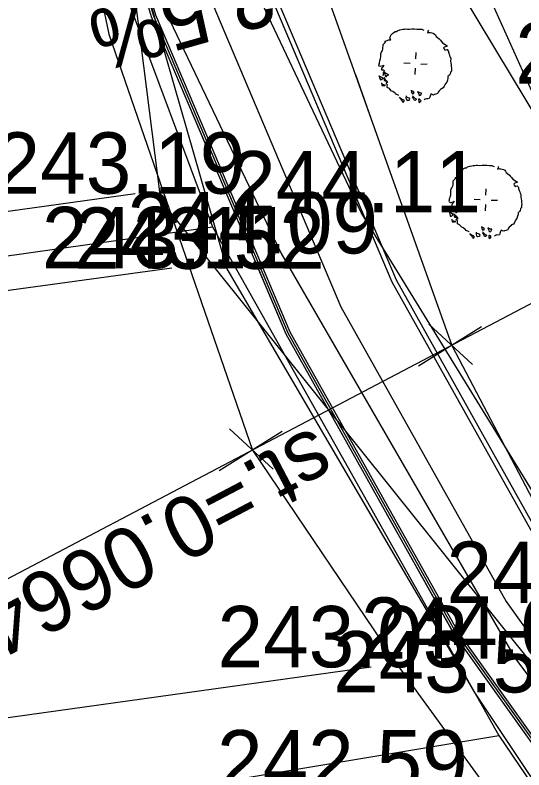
# Model space of a CAD drawing. Extents: x -601754 to -601440, y -1201912 to -1200862.
# Drawn here: x -601633.19 to -601616.59, y -1200964.76 to -1200940.13 of the extents above; entities that cross this region are included whole.
import ezdxf

# ---------------------------------------------------------------- set-up
doc = ezdxf.new("R2010")
doc.units = 0
for name, color, linetype in [('Hranice parcel', 7, 'Continuous'), ('u_drén', 7, 'Continuous'), ('u_hrany', 7, 'Continuous'), ('u_krizky', 7, 'Continuous'), ('u_návrh', 7, 'Continuous'), ('u_oblouky', 7, 'Continuous'), ('u_osa', 7, 'Continuous'), ('u_pricne_cesta', 7, 'Continuous'), ('u_sklony', 7, 'Continuous'), ('u_terénní úpravy', 7, 'Continuous'), ('u_vysadba_SO_101', 7, 'Continuous'), ('u_vyska', 7, 'Continuous')]:
    doc.layers.add(name, color=color, linetype=linetype)

msp = doc.modelspace()

# ---------------------------------------------------------------- linework, layer by layer
at = {"layer": 'Hranice parcel'}
for p, q in [((-601632.72, -1200931.05), (-601626.75, -1200947.04)), ((-601620.33, -1200933.7), (-601616.34, -1200942.61)), ((-601626.75, -1200947.04), (-601617.41, -1200963.63))]:
    msp.add_line(p, q, dxfattribs=at)
for points in [[(-601611.28, -1200963.08), (-601614.07, -1200959.31), (-601621.9, -1200946.57), (-601626.39, -1200937.08), (-601630.02, -1200926.25), (-601631.65, -1200918.55), (-601633.57, -1200899.96), (-601633.33, -1200887.98), (-601632.07, -1200885.6), (-601629.11, -1200882.26)], [(-601751.585, -1200963.007), (-601675.86, -1200953.98), (-601626.75, -1200947.04)], [(-601751.585, -1200977.923), (-601676.3, -1200973.45), (-601617.41, -1200963.63)], [(-601617.41, -1200963.63), (-601609.12, -1200975.86), (-601608.55, -1200976.64)]]:
    msp.add_lwpolyline(points, dxfattribs=at)
at = {"layer": 'u_drén'}
msp.add_lwpolyline([(-601630.738, -1200933.27), (-601628.676, -1200940.153), (-601624.291, -1200950.498), (-601618.798, -1200960.3), (-601612.295, -1200969.398), (-601587.744, -1201000.039)], dxfattribs=at)
at = {"layer": 'u_hrany'}
for points in [[(-601637.65, -1200892.44), (-601636.56, -1200901.01), (-601634.78, -1200919.25), (-601632.6, -1200928.32), (-601629.33, -1200937.82), (-601624.51, -1200947.91), (-601616.86, -1200961.13), (-601606.97, -1200974.25), (-601596.82, -1200985.88), (-601582.46, -1201002.22), (-601574.49, -1201012.64), (-601569.33, -1201022.81), (-601566.79, -1201038.25), (-601566.21, -1201048.21)], [(-601568.57, -1201015.08), (-601571.45, -1201010.54), (-601577.11, -1201003.42), (-601594.37, -1200984.29), (-601604.5, -1200972.6), (-601614.07, -1200959.31), (-601621.9, -1200946.57), (-601626.39, -1200937.08), (-601629.97, -1200926.48)], [(-601621.22, -1200935.1), (-601608.09, -1200956.91)], [(-601629.33, -1200937.82), (-601626.28, -1200948.41), (-601618.2, -1200962.23), (-601609.12, -1200975.86), (-601600.84, -1200990.01)], [(-601629.27, -1200945.96), (-601650.16, -1200948.87)], [(-601628.07, -1200948.39), (-601645.88, -1200950.82)], [(-601621.57, -1200961.41), (-601640.21, -1200964)]]:
    msp.add_lwpolyline(points, dxfattribs=at)
at = {"layer": 'u_krizky'}
for p, q in [((-601617.969, -1200950.305), (-601620.022, -1200951.585)), ((-601618.263, -1200951.531), (-601619.689, -1200950.212)), ((-601624.475, -1200953.722), (-601626.528, -1200955.002)), ((-601624.768, -1200954.949), (-601626.195, -1200953.629))]:
    msp.add_line(p, q, dxfattribs=at)
at = {"layer": 'u_návrh'}
for points in [[(-601634.025, -1200887.577), (-601630.185, -1200917.812), (-601628.225, -1200928.505), (-601625.119, -1200938.871), (-601620.896, -1200948.834), (-601615.607, -1200958.274), (-601609.285, -1200967.119), (-601584.73, -1200997.764)], [(-601633.876, -1200887.558), (-601630.036, -1200917.789), (-601628.079, -1200928.47), (-601624.978, -1200938.82), (-601620.761, -1200948.768), (-601615.48, -1200958.194), (-601609.165, -1200967.028), (-601578.723, -1201005.021)], [(-601637.844, -1200888.062), (-601633.991, -1200918.402), (-601631.974, -1200929.408), (-601628.747, -1200940.179), (-601624.358, -1200950.531), (-601618.862, -1200960.341), (-601612.355, -1200969.444), (-601581.832, -1201007.537)], [(-601637.695, -1200888.043), (-601633.842, -1200918.379), (-601631.828, -1200929.372), (-601628.605, -1200940.128), (-601624.223, -1200950.465), (-601618.735, -1200960.26), (-601612.236, -1200969.353), (-601587.617, -1201000.078)]]:
    msp.add_lwpolyline(points, dxfattribs=at)
at = {"layer": 'u_oblouky'}
for p in [(-601632.013, -1200918.095), (-601610.76, -1200968.236)]:
    msp.add_line(p, (-601628.449, -1200946.159), dxfattribs=at)
at = {"layer": 'u_osa'}
msp.add_lwpolyline([(-601635.86, -1200887.81), (-601632.013, -1200918.095), (-601630.026, -1200928.939), (-601626.862, -1200939.5), (-601622.56, -1200949.65), (-601617.171, -1200959.267), (-601610.76, -1200968.236), (-601578.672, -1201008.284), (-601575.031, -1201013.469), (-601572.075, -1201019.074), (-601569.852, -1201025.007), (-601568.398, -1201031.174), (-601566.15, -1201044.408), (-601565.576, -1201049.148), (-601565.456, -1201053.922), (-601565.793, -1201058.685), (-601566.228, -1201062.343), (-601567.198, -1201067.854), (-601568.778, -1201073.221), (-601570.948, -1201078.378), (-601573.681, -1201083.261), (-601575.226, -1201085.692), (-601578.132, -1201090.011)], dxfattribs=at)
at = {"layer": 'u_pricne_cesta'}
msp.add_lwpolyline([(-601603.486, -1200942.791), (-601621.191, -1200952.092), (-601638.897, -1200961.394)], dxfattribs=at)
at = {"layer": 'u_sklony'}
for p, q in [((-601622.087, -1200942.068), (-601621.501, -1200943.711)), ((-601627.735, -1200942.565), (-601626.937, -1200944.449)), ((-601625.405, -1200948.062), (-601624.502, -1200950.193)), ((-601621.082, -1200956.378), (-601618.965, -1200960.156))]:
    msp.add_line(p, q, dxfattribs=at)
at = {"layer": 'u_terénní úpravy'}
for points in [[(-601638.582, -1200888.156), (-601634.493, -1200918.503), (-601632.607, -1200929.56), (-601631.638, -1200933.524), (-601630.127, -1200940.76), (-601625.442, -1200954.325), (-601625.442, -1200954.325), (-601620.62, -1200961.457), (-601614.291, -1200970.175), (-601602.86, -1200984.783)], [(-601623.651, -1200937.04), (-601622.862, -1200939.893), (-601618.936, -1200950.908), (-601615.274, -1200957.893), (-601609.075, -1200966.053), (-601604.07, -1200972.745), (-601597.484, -1200980.476), (-601592.22, -1200988.176), (-601585.958, -1200994.904), (-601578.723, -1201005.021), (-601574.41, -1201008.093), (-601573.524, -1201008.969), (-601571.743, -1201011.837), (-601569.512, -1201016.171), (-601566.023, -1201016.188)]]:
    msp.add_lwpolyline(points, dxfattribs=at)
at = {"layer": 'u_vysadba_SO_101'}
for points in [[(-601621.115, -1200941.019), (-601621.114, -1200940.989), (-601621.054, -1200940.963), (-601621.024, -1200940.95), (-601620.994, -1200940.937), (-601620.964, -1200940.939), (-601620.935, -1200940.94), (-601620.948, -1200940.91), (-601620.961, -1200940.88), (-601620.944, -1200940.837), (-601620.927, -1200940.794), (-601620.896, -1200940.752), (-601620.865, -1200940.724), (-601620.834, -1200940.697), (-601620.789, -1200940.67), (-601620.745, -1200940.672), (-601620.715, -1200940.644), (-601620.64, -1200940.619), (-601620.581, -1200940.608), (-601620.536, -1200940.595), (-601620.478, -1200940.598), (-601620.433, -1200940.586), (-601620.389, -1200940.588), (-601620.316, -1200940.592), (-601620.243, -1200940.581), (-601620.17, -1200940.585), (-601620.082, -1200940.59), (-601619.994, -1200940.595), (-601619.921, -1200940.598), (-601619.878, -1200940.615), (-601619.85, -1200940.631)], [(-601619.703, -1200940.625), (-601619.719, -1200940.653), (-601619.721, -1200940.682), (-601619.737, -1200940.711), (-601619.692, -1200940.698), (-601619.663, -1200940.7), (-601619.634, -1200940.701), (-601619.591, -1200940.718), (-601619.547, -1200940.721), (-601619.505, -1200940.752), (-601619.477, -1200940.783), (-601619.45, -1200940.828), (-601619.408, -1200940.86), (-601619.352, -1200940.907), (-601619.311, -1200940.953), (-601619.283, -1200940.984), (-601619.242, -1200941.044), (-601619.185, -1200941.077), (-601619.143, -1200941.108), (-601619.1, -1200941.125), (-601619.102, -1200941.154)], [(-601621.115, -1200941.019), (-601621.116, -1200941.033), (-601621.162, -1200941.075), (-601621.193, -1200941.102), (-601621.195, -1200941.146), (-601621.197, -1200941.19), (-601621.2, -1200941.248), (-601621.217, -1200941.291), (-601621.233, -1200941.32), (-601621.25, -1200941.348), (-601621.267, -1200941.406), (-601621.269, -1200941.435), (-601621.272, -1200941.493), (-601621.274, -1200941.537), (-601621.276, -1200941.566), (-601621.294, -1200941.639), (-601621.311, -1200941.682), (-601621.313, -1200941.726), (-601621.33, -1200941.754), (-601621.317, -1200941.784), (-601621.274, -1200941.801), (-601621.184, -1200941.776), (-601621.154, -1200941.763), (-601621.187, -1200941.82), (-601621.217, -1200941.848), (-601621.234, -1200941.876), (-601621.236, -1200941.92), (-601621.207, -1200941.922), (-601621.163, -1200941.924), (-601621.15, -1200941.954), (-601621.167, -1200941.997), (-601621.183, -1200942.025), (-601621.185, -1200942.069), (-601621.188, -1200942.113)], [(-601619.102, -1200941.154), (-601619.146, -1200941.167), (-601619.191, -1200941.179), (-601619.207, -1200941.207), (-601619.194, -1200941.237), (-601619.167, -1200941.283), (-601619.137, -1200941.27), (-601619.092, -1200941.257), (-601619.065, -1200941.288), (-601619.052, -1200941.318), (-601619.053, -1200941.347), (-601619.027, -1200941.407), (-601619.015, -1200941.452), (-601619.002, -1200941.496), (-601618.976, -1200941.542), (-601618.977, -1200941.571), (-601618.979, -1200941.615), (-601618.981, -1200941.644), (-601618.969, -1200941.688), (-601618.957, -1200941.748), (-601618.96, -1200941.806), (-601618.949, -1200941.865), (-601618.95, -1200941.894), (-601618.952, -1200941.924), (-601618.954, -1200941.967), (-601618.985, -1200941.995), (-601618.986, -1200942.024), (-601619.003, -1200942.067), (-601619.019, -1200942.096), (-601619.066, -1200942.137), (-601619.069, -1200942.196), (-601619.086, -1200942.253), (-601619.105, -1200942.325), (-601619.152, -1200942.382), (-601619.185, -1200942.453), (-601619.217, -1200942.51), (-601619.277, -1200942.536), (-601619.308, -1200942.564), (-601619.354, -1200942.605), (-601619.385, -1200942.647), (-601619.402, -1200942.69), (-601619.462, -1200942.717), (-601619.507, -1200942.729), (-601619.537, -1200942.742), (-601619.58, -1200942.725), (-601619.623, -1200942.708), (-601619.64, -1200942.751), (-601619.658, -1200942.809), (-601619.674, -1200942.852), (-601619.719, -1200942.864), (-601619.763, -1200942.862)], [(-601620.116, -1200941.56), (-601620.105, -1200941.356)], [(-601620.299, -1200941.711), (-601620.504, -1200941.701)], [(-601620.132, -1200941.867), (-601620.143, -1200942.071)], [(-601619.949, -1200941.73), (-601619.744, -1200941.726)], [(-601621.319, -1200942.106), (-601621.306, -1200942.136), (-601621.294, -1200942.181), (-601621.281, -1200942.211), (-601621.282, -1200942.24), (-601621.254, -1200942.256), (-601621.223, -1200942.228), (-601621.177, -1200942.187), (-601621.206, -1200942.185), (-601621.248, -1200942.154), (-601621.291, -1200942.137)], [(-601621.161, -1200942.173), (-601621.12, -1200942.219), (-601621.078, -1200942.265), (-601621.036, -1200942.297)], [(-601621.137, -1200941.984), (-601621.139, -1200942.028), (-601621.126, -1200942.058), (-601621.114, -1200942.102), (-601621.101, -1200942.132), (-601621.071, -1200942.134), (-601621.055, -1200942.105), (-601620.995, -1200942.079), (-601621.038, -1200942.062), (-601621.067, -1200942.046), (-601621.124, -1200942.014)], [(-601621.229, -1200942.345), (-601621.219, -1200942.433), (-601621.175, -1200942.436), (-601621.146, -1200942.437), (-601621.101, -1200942.425), (-601621.159, -1200942.407), (-601621.203, -1200942.405), (-601621.216, -1200942.375)], [(-601621.036, -1200942.297), (-601621.065, -1200942.295), (-601621.095, -1200942.294), (-601621.124, -1200942.292), (-601621.137, -1200942.262), (-601621.135, -1200942.233), (-601621.148, -1200942.203)], [(-601620.665, -1200942.756), (-601620.708, -1200942.739), (-601620.736, -1200942.722), (-601620.766, -1200942.721), (-601620.793, -1200942.676), (-601620.821, -1200942.659), (-601620.863, -1200942.628), (-601620.906, -1200942.611), (-601620.948, -1200942.565), (-601620.975, -1200942.534), (-601621.047, -1200942.501), (-601621.045, -1200942.457), (-601621.042, -1200942.413), (-601621.055, -1200942.383), (-601621.084, -1200942.367), (-601621.052, -1200942.325), (-601621.023, -1200942.327)], [(-601620.261, -1200942.587), (-601620.25, -1200942.66), (-601620.223, -1200942.706), (-601620.179, -1200942.693), (-601620.177, -1200942.664), (-601620.175, -1200942.635), (-601620.218, -1200942.618), (-601620.247, -1200942.602)], [(-601620.058, -1200942.627), (-601620.032, -1200942.686), (-601620.019, -1200942.731), (-601619.992, -1200942.762), (-601619.962, -1200942.749), (-601619.93, -1200942.706), (-601619.929, -1200942.677), (-601619.973, -1200942.675), (-601620.001, -1200942.659), (-601620.029, -1200942.643), (-601620.059, -1200942.641)], [(-601620.654, -1200942.815), (-601620.557, -1200942.937), (-601620.531, -1200942.982), (-601620.499, -1200942.94), (-601620.498, -1200942.911), (-601620.526, -1200942.895), (-601620.569, -1200942.878), (-601620.597, -1200942.862), (-601620.626, -1200942.845)], [(-601620.431, -1200942.768), (-601620.435, -1200942.841), (-601620.423, -1200942.885), (-601620.395, -1200942.916), (-601620.336, -1200942.905), (-601620.305, -1200942.877), (-601620.318, -1200942.847), (-601620.361, -1200942.83), (-601620.405, -1200942.813)], [(-601620.226, -1200942.764), (-601620.142, -1200942.842), (-601620.114, -1200942.858), (-601620.101, -1200942.888), (-601620.132, -1200942.915), (-601620.161, -1200942.914), (-601620.174, -1200942.884), (-601620.201, -1200942.839), (-601620.229, -1200942.808)], [(-601620.027, -1200942.877), (-601620.016, -1200942.951), (-601620.003, -1200942.981), (-601619.973, -1200942.968), (-601619.942, -1200942.926), (-601619.97, -1200942.895), (-601619.998, -1200942.879), (-601620.027, -1200942.877)], [(-601619.763, -1200942.862), (-601619.807, -1200942.874), (-601619.838, -1200942.902)], [(-601618.825, -1200945.463), (-601618.824, -1200945.434), (-601618.764, -1200945.408), (-601618.734, -1200945.395), (-601618.704, -1200945.382), (-601618.675, -1200945.384), (-601618.645, -1200945.385), (-601618.659, -1200945.355), (-601618.672, -1200945.325), (-601618.655, -1200945.282), (-601618.638, -1200945.239), (-601618.606, -1200945.197), (-601618.576, -1200945.169), (-601618.545, -1200945.142), (-601618.499, -1200945.115), (-601618.456, -1200945.117), (-601618.425, -1200945.089), (-601618.35, -1200945.064), (-601618.291, -1200945.052), (-601618.247, -1200945.04), (-601618.188, -1200945.043), (-601618.144, -1200945.031), (-601618.1, -1200945.033), (-601618.027, -1200945.037), (-601617.953, -1200945.026), (-601617.88, -1200945.03), (-601617.792, -1200945.035), (-601617.705, -1200945.039), (-601617.632, -1200945.043), (-601617.589, -1200945.06), (-601617.56, -1200945.076)], [(-601617.413, -1200945.07), (-601617.43, -1200945.098), (-601617.431, -1200945.127), (-601617.447, -1200945.156), (-601617.403, -1200945.143), (-601617.374, -1200945.145), (-601617.344, -1200945.146), (-601617.301, -1200945.163), (-601617.257, -1200945.166), (-601617.215, -1200945.197), (-601617.188, -1200945.228), (-601617.161, -1200945.273), (-601617.118, -1200945.305), (-601617.062, -1200945.352), (-601617.021, -1200945.398), (-601616.993, -1200945.428), (-601616.952, -1200945.489), (-601616.896, -1200945.522), (-601616.853, -1200945.553), (-601616.81, -1200945.57), (-601616.812, -1200945.599)], [(-601618.825, -1200945.463), (-601618.826, -1200945.478), (-601618.872, -1200945.52), (-601618.903, -1200945.547), (-601618.905, -1200945.591), (-601618.908, -1200945.635), (-601618.911, -1200945.693), (-601618.928, -1200945.736), (-601618.944, -1200945.765), (-601618.96, -1200945.793), (-601618.978, -1200945.851), (-601618.979, -1200945.88), (-601618.982, -1200945.938), (-601618.985, -1200945.982), (-601618.986, -1200946.011), (-601619.005, -1200946.084), (-601619.021, -1200946.127), (-601619.024, -1200946.17), (-601619.04, -1200946.199), (-601619.027, -1200946.229), (-601618.984, -1200946.246), (-601618.895, -1200946.221), (-601618.865, -1200946.208), (-601618.897, -1200946.265), (-601618.928, -1200946.293), (-601618.944, -1200946.321), (-601618.946, -1200946.365), (-601618.917, -1200946.366), (-601618.873, -1200946.369), (-601618.86, -1200946.399), (-601618.877, -1200946.442), (-601618.893, -1200946.47), (-601618.895, -1200946.514), (-601618.898, -1200946.558)], [(-601616.812, -1200945.599), (-601616.856, -1200945.611), (-601616.901, -1200945.624), (-601616.917, -1200945.652), (-601616.904, -1200945.682), (-601616.877, -1200945.727), (-601616.847, -1200945.714), (-601616.803, -1200945.702), (-601616.775, -1200945.733), (-601616.762, -1200945.763), (-601616.763, -1200945.792), (-601616.737, -1200945.852), (-601616.725, -1200945.897), (-601616.713, -1200945.941), (-601616.686, -1200945.987), (-601616.687, -1200946.016), (-601616.69, -1200946.06), (-601616.691, -1200946.089), (-601616.679, -1200946.133), (-601616.667, -1200946.192), (-601616.671, -1200946.251), (-601616.659, -1200946.31), (-601616.661, -1200946.339), (-601616.662, -1200946.368), (-601616.664, -1200946.412), (-601616.695, -1200946.44), (-601616.697, -1200946.469), (-601616.714, -1200946.512), (-601616.73, -1200946.541), (-601616.776, -1200946.582), (-601616.779, -1200946.641), (-601616.797, -1200946.698), (-601616.815, -1200946.77), (-601616.862, -1200946.826), (-601616.895, -1200946.898), (-601616.927, -1200946.955), (-601616.987, -1200946.981), (-601617.018, -1200947.009), (-601617.064, -1200947.05), (-601617.096, -1200947.092), (-601617.113, -1200947.135), (-601617.173, -1200947.161), (-601617.217, -1200947.174), (-601617.247, -1200947.187), (-601617.29, -1200947.17), (-601617.333, -1200947.153), (-601617.35, -1200947.196), (-601617.368, -1200947.254), (-601617.385, -1200947.297), (-601617.429, -1200947.309), (-601617.473, -1200947.307)], [(-601617.826, -1200946.005), (-601617.815, -1200945.801)], [(-601618.01, -1200946.156), (-601618.214, -1200946.146)], [(-601617.842, -1200946.312), (-601617.853, -1200946.516)], [(-601617.659, -1200946.175), (-601617.454, -1200946.171)], [(-601619.029, -1200946.551), (-601619.016, -1200946.581), (-601619.004, -1200946.625), (-601618.991, -1200946.655), (-601618.992, -1200946.685), (-601618.964, -1200946.701), (-601618.933, -1200946.673), (-601618.887, -1200946.632), (-601618.916, -1200946.63), (-601618.959, -1200946.599), (-601619.002, -1200946.582)], [(-601618.847, -1200946.429), (-601618.849, -1200946.473), (-601618.836, -1200946.503), (-601618.824, -1200946.547), (-601618.811, -1200946.577), (-601618.782, -1200946.579), (-601618.766, -1200946.55), (-601618.706, -1200946.524), (-601618.749, -1200946.507), (-601618.777, -1200946.491), (-601618.834, -1200946.459)], [(-601618.939, -1200946.79), (-601618.929, -1200946.878), (-601618.886, -1200946.881), (-601618.856, -1200946.882), (-601618.812, -1200946.87), (-601618.869, -1200946.852), (-601618.913, -1200946.85), (-601618.926, -1200946.82)], [(-601618.872, -1200946.618), (-601618.83, -1200946.664), (-601618.789, -1200946.71), (-601618.746, -1200946.742)], [(-601618.746, -1200946.742), (-601618.776, -1200946.74), (-601618.805, -1200946.738), (-601618.834, -1200946.737), (-601618.847, -1200946.707), (-601618.846, -1200946.678), (-601618.859, -1200946.648)], [(-601618.375, -1200947.2), (-601618.418, -1200947.184), (-601618.447, -1200947.167), (-601618.476, -1200947.166), (-601618.503, -1200947.12), (-601618.531, -1200947.104), (-601618.574, -1200947.073), (-601618.617, -1200947.056), (-601618.658, -1200947.01), (-601618.686, -1200946.979), (-601618.757, -1200946.946), (-601618.755, -1200946.902), (-601618.753, -1200946.858), (-601618.766, -1200946.828), (-601618.794, -1200946.812), (-601618.763, -1200946.77), (-601618.733, -1200946.772)], [(-601617.971, -1200947.031), (-601617.96, -1200947.105), (-601617.933, -1200947.151), (-601617.889, -1200947.138), (-601617.887, -1200947.109), (-601617.886, -1200947.08), (-601617.929, -1200947.063), (-601617.957, -1200947.047)], [(-601617.768, -1200947.071), (-601617.742, -1200947.131), (-601617.73, -1200947.176), (-601617.702, -1200947.207), (-601617.672, -1200947.194), (-601617.641, -1200947.151), (-601617.639, -1200947.122), (-601617.683, -1200947.12), (-601617.711, -1200947.104), (-601617.74, -1200947.088), (-601617.769, -1200947.086)], [(-601618.364, -1200947.26), (-601618.268, -1200947.382), (-601618.241, -1200947.427), (-601618.209, -1200947.385), (-601618.208, -1200947.356), (-601618.236, -1200947.34), (-601618.279, -1200947.323), (-601618.308, -1200947.307), (-601618.336, -1200947.29)], [(-601618.142, -1200947.213), (-601618.146, -1200947.286), (-601618.133, -1200947.33), (-601618.106, -1200947.361), (-601618.046, -1200947.35), (-601618.016, -1200947.322), (-601618.029, -1200947.292), (-601618.072, -1200947.275), (-601618.115, -1200947.258)], [(-601617.936, -1200947.209), (-601617.853, -1200947.287), (-601617.824, -1200947.303), (-601617.811, -1200947.333), (-601617.842, -1200947.36), (-601617.871, -1200947.359), (-601617.884, -1200947.329), (-601617.911, -1200947.284), (-601617.939, -1200947.253)], [(-601617.737, -1200947.322), (-601617.727, -1200947.396), (-601617.714, -1200947.426), (-601617.684, -1200947.413), (-601617.652, -1200947.37), (-601617.68, -1200947.34), (-601617.708, -1200947.324), (-601617.737, -1200947.322)], [(-601617.473, -1200947.307), (-601617.518, -1200947.319), (-601617.548, -1200947.347)]]:
    msp.add_lwpolyline(points, dxfattribs=at)

# ---------------------------------------------------------------- texts
at = {"layer": 'u_pricne_cesta'}
msp.add_text('st.=0.06642', height=2, rotation=207.7145, dxfattribs=at).set_placement((-601623.44, -1200953.542))
at = {"layer": 'u_sklony'}
msp.add_text('2,5%', height=2, rotation=195.799, dxfattribs=at).set_placement((-601625.061, -1200938.417))
at = {"layer": 'u_vyska'}
for s, p in [('247.20', (-601616.87, -1200942.37)), ('243.19', (-601633.859, -1200945.96)), ('244.11', (-601626.172, -1200946.57)), ('244.09', (-601629.528, -1200947.91)), ('243.11', (-601632.314, -1200948.39)), ('243.52', (-601631.264, -1200948.41)), ('244.03', (-601619.113, -1200959.31)), ('244.03', (-601621.903, -1200961.13)), ('243.03', (-601626.585, -1200961.41)), ('243.51', (-601622.815, -1200962.23)), ('242.59', (-601626.6, -1200965.46))]:
    msp.add_text(s, height=2, dxfattribs=at).set_placement(p)

doc.saveas('drawing.dxf')
